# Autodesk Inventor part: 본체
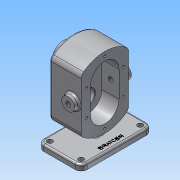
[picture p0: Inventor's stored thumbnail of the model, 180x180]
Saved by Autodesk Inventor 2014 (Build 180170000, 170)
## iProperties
Created: 2019-03
Part Number: 본체
Material: 알루미늄 6061
Document SubType Name: Modeling
Designer: net
Density: 2.71 g/cm^3
Appearance: 알루미늄 - 평지
Mass: 1191.56 g
Surface Area: 719.273 cm^2
Volume: 439.69 cm^3
Author: net
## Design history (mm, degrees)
sketch "스케치1"
  geometry: L1 (40, -60)-(-40, -60); L2 (-40, -40)-(-40, 40); L3 (-40, 60)-(40, 60); L4 (40, 40)-(40, -40); L5 (40, -60)-(-40, 60); L6 (-40, -60)-(40, 60); A1 r 60 centre (0, 0) between (36, 48) and (-36, 48); A2 r 60 centre (0, 0) between (-36, -48) and (36, -48); A3 r 10 centre (-30, 40) between (-36, 48) and (-40, 40); A4 r 10 centre (30, 40) between (40, 40) and (36, 48); A5 r 10 centre (30, -40) between (36, -48) and (40, -40); A6 r 10 centre (-30, -40) between (-40, -40) and (-36, -48); 5 further points
  constraints: 16 point on circle, 12 end point, 8 point on line, 8 tangent, 6 centre point, 3 equal radius, 2 coincident, 2 midpoint, 2 parallel, 1 horizontal, 1 perpendicular
  dimensions: "d0" = 80 distance of L3.start L3.end; "d1" = 120 distance of L1.end L3.start; "d3" = 60 radius of A1; "d4" = 60 radius of A2; "d5" = 10 radius of A3
extrude "돌출1" new body sketch "스케치1" stored distance "d6" = 53; taper "d7" = 0 deg
sketch "스케치3"
  geometry: L1 (-40, -40)-(40, -40) reference; L2 (-22, 0)-(22, 0); L3 (-22, -24)-(22, -24); L4 (22, 24)-(-22, 24); A1 r 60 centre (0, 0) between (48, -36) and (48, 36) reference; A2 r 60 centre (0, 0) between (-48, 36) and (-48, -36) reference; A3 r 24 centre (-22, 0) between (-22, 24) and (-22, -24); A4 r 24 centre (22, 0) between (22, -24) and (22, 24); 1 further point
  constraints: 8 end point, 4 point on circle, 4 tangent, 2 centre point, 2 parallel, 1 coincident, 1 midpoint
  dimensions: "d10" = 24 radius of A3; "d11" = 44 distance of L2.start L2.end; "d12" = 22 distance of L2.start A2.centre
extrude "돌출2" cut sketch "스케치3" distance "d13" = 29; taper "d14" = 0 deg
sketch "스케치2"
  geometry: L1 (-22, -24)-(22, -24) reference; L2 (22, 24)-(-22, 24) reference; C1 r 19 at (22, 0); C2 r 14 at (22, 0); A1 r 60 centre (0, 0) between (48, -36) and (48, 36) reference; A2 r 24 centre (-22, 0) between (-22, 24) and (-22, -24) reference; A3 r 24 centre (22, 0) between (22, -24) and (22, 24) reference
  constraints: 2 centre point, 2 coincident, 1 horizontal alignment
  dimensions: "d8" = 38 diameter of C1; "d9" = 28 diameter of C2
extrude "돌출3" join sketch "스케치2" distance "d15" = 17; taper "d16" = 0 deg
sketch "스케치4"
  geometry: C1 r 19 at (0, 0) reference; C2 r 14 at (0, 0); 1 further point
  constraints: 1 centre point, 1 coincident
  dimensions: "d17" = 28 diameter of C2
extrude "돌출4" cut sketch "스케치4" distance "d18" = 7.3; taper "d19" = 0 deg
sketch "스케치5"
  geometry: C1 r 12.5 at (-22, 0); C2 r 12.5 at (22, 0); A1 r 24 centre (22, 0) between (22, -24) and (22, 24) reference; A2 r 24 centre (-22, 0) between (-22, 24) and (-22, -24) reference; 1 further point
  constraints: 2 centre point, 2 coincident
  dimensions: "d20" = 25 diameter of C1; "d21" = 25 diameter of C2
extrude "돌출5" cut sketch "스케치5" distance "d22" = 15; taper "d23" = 0 deg
sketch "스케치6"
  geometry: C1 r 14 at (0, 0) reference; C2 r 8.5 at (0, 0); 1 further point
  constraints: 1 centre point, 1 coincident
  dimensions: "d24" = 17 diameter of C2
extrude "돌출6" cut sketch "스케치6" stored distance "d25" = 15; taper "d26" = 0 deg
fillet "모깎기1" dims "d27" = 0.5
chamfer "모따기1" distance "d28" = 0.7; stored, may be unused: second distance "d29" = 2, angle "d30" = 30 deg
sketch "스케치7"
  geometry: L1 (53, 80)-(53, 0) reference; C1 r 11 at (39, 40); 1 further point
  constraints: 1 centre point, 1 horizontal alignment
  dimensions: "d41" = 22 diameter of C1; "d42" = 14 distance from line of C1.centre L1
extrude "돌출7" join sketch "스케치7" distance "d32" = 8; taper "d33" = 0 deg
sketch "스케치9"
  geometry: C1 r 11 at (0, 0) reference; 2 further points
  constraints: 1 coincident
hole "구멍2" sketch "스케치9" at (0, 0) diameter "d43" = 8.376; stored, may be unused: countersink angle "d47" = 90 deg, drill point angle "d49" = 118 deg; dims "d44" = 6, "d45" = 4, "d46" = 2, "d48" = 8
sketch "스케치10" dims "d53" = 62
  geometry: A1 r 24 centre (22, 0) between (22, -24) and (22, 24) reference; A2 r 24 centre (-22, 0) between (-22, 24) and (-22, -24) reference; A3 r 60 centre (0, 0) between (48, -36) and (48, 36) reference; A4 r 31 centre (-22, 0) between (-22, 31) and (-53, 0); 5 further points
  constraints: 5 horizontal alignment, 3 point on circle, 2 coincident, 2 vertical alignment, 1 centre point, 2 other
  dimensions: "d50" = 22 horizontal distance of A3.centre A4.start; "d51" = 44 distance of A4.start point (22, 31); "d52" = 62 diameter of A4
hole "구멍3" sketch "스케치10" at (-22, 31), (22, 31), (-53, 0), (-22, -31), (22, -31), (53, 0) diameter "d54" = 4.134; stored, may be unused: countersink angle "d58" = 90 deg, drill point angle "d60" = 118 deg; dims "d55" = 10, "d56" = 4, "d57" = 2, "d59" = 12
chamfer "모따기2" distance "d61" = 1; stored, may be unused: second distance "d62" = 2, angle "d63" = 30 deg
fillet "모깎기2" dims "d64" = 3
node "작업 평면1"
sketch "스케치11"
  geometry: L1 (-26.5, 36)-(-26.5, -36) reference; L2 (36.5, -60)-(-16.5, -60); L3 (-26.5, -50)-(-26.5, 50); L4 (-16.5, 60)-(36.5, 60); L5 (46.5, 50)-(46.5, -50); L6 (46.5, -60)-(-26.5, 60); L7 (-26.5, -60)-(46.5, 60); C1 r 4.5 at (-16.5, 50); C2 r 4.5 at (36.5, 50); C3 r 4.5 at (36.5, -50); C4 r 4.5 at (-16.5, -50); A1 r 10 centre (-16.5, 50) between (-16.5, 60) and (-26.5, 50); A2 r 10 centre (36.5, 50) between (46.5, 50) and (36.5, 60); A3 r 10 centre (36.5, -50) between (36.5, -60) and (46.5, -50); A4 r 10 centre (-16.5, -50) between (-26.5, -50) and (-16.5, -60); 3 further points
  constraints: 12 end point, 9 point on line, 8 centre point, 8 point on circle, 8 tangent, 4 coincident, 3 equal radius, 3 midpoint, 2 parallel, 1 horizontal, 1 horizontal alignment, 1 perpendicular
  dimensions: "d66" = 73 distance of L6.end L7.end; "d67" = 120 distance of L7.end L6.start; "d68" = 10 radius of A1; "d69" = 9 diameter of C1; "d70" = 9 diameter of C2; "d71" = 9 diameter of C3; "d72" = 9 diameter of C4
extrude "돌출8" join sketch "스케치11" distance "d73" = 10; taper "d74" = 0 deg
sketch "스케치12"
  geometry: L1 (-26.5, 50)-(-26.5, -50) reference; L2 (16.5, -6)-(-26.5, -6); L3 (-26.5, -6)-(-26.5, 6); L4 (-26.5, 6)-(16.5, 6); L5 (16.5, 6)-(16.5, -6); L6 (16.5, -6)-(-26.5, 6); L7 (-26.5, -6)-(16.5, 6); 3 further points
  constraints: 12 end point, 3 midpoint, 2 parallel, 1 horizontal, 1 horizontal alignment, 1 perpendicular, 1 point on line
  dimensions: "d75" = 12 distance of L2.end L3.end; "d76" = 43 distance of L3.end L4.end
extrude "돌출9" join sketch "스케치12" stored distance "d77" = 10; taper "d78" = 0 deg
fillet "모깎기3" dims "d79" = 3
fillet "모깎기4" dims "d80" = 3
fillet "모깎기5" dims "d81" = 3
sketch "스케치13"
  geometry: L1 (-16.5, -60)-(36.5, -60) reference; L2 (46.5, -50)-(46.5, 50) reference; 2 further points
  constraints: 1 other
  dimensions: "d82" = 60 distance from line of L1 point (36.5, 0); "d83" = 10 distance from line of L2 point (36.5, 0)
feature "엠보싱1" sketch "스케치13" dims "d0" = 80, "d1" = 120, "d3" = 60, "d4" = 60, "d5" = 10, "d84" = 0.5, "d85" = 0
node "솔리드1"
mirror "대칭1"
node "투영된 루프1"
other parameters: "d65" = -78
